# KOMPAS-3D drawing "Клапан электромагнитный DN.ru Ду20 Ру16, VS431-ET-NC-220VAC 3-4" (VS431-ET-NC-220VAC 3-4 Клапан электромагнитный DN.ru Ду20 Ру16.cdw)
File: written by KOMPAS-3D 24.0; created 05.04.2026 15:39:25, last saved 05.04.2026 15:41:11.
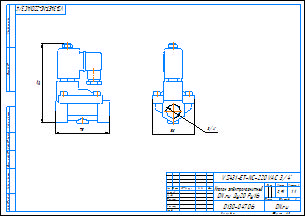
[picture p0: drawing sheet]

Document properties: c3d_UniqueCompID: ef56311e-7521-43dc-8291-0e6108b3d81d; Автор: artio; Класс точности: c; Знак неуказанной шероховатости: Шероховатость не задана; Рассекать на разрезах: Да; Автор: artio; Форматы листов документа: A3; Полное имя файла: VS431-ET-NC-220VAC 3-4 Клапан электромагнитный DN.ru Ду20 Ру16.m3d; Масса: 0.907; Наименование: Клапан электромагнитный DN.ru Ду20 Ру16; Количество листов документа: 1; Примечание: D130-04706

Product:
- Body: Тело 1  | qty 1
    Масса: 1.198355
- Part/product: Клапан электромагнитный DN.ru Ду20 Ру16  | designation VS431-ET-NC-220VAC 3-4
    Масса: 0.907
    Раздел спецификации: Прочие изделия
    Примечание: D130-04706
    additional columns: ef56311e-7521-43dc-8291-0e6108b3d81d; artio; c; Шероховатость не задана; Да

Views: Вид 1, Спереди, Проекционный вид 2
Referenced files in C:\Users\artio\OneDrive\Рабочий стол\Клапан электромагнитный DN.ru\VS431\VS431-ET-NC\: VS431-ET-NC-220VAC 3-4 Клапан электромагнитный DN.ru Ду20 Ру16.m3d
Referenced files in C:\Users\artio\OneDrive\Рабочий стол\Клапан электромагнитный DN.ru\VS431\VS431-ET-NC\VS431-ET-NC-220VAC\Ду20\: VS431-ET-NC-220VAC 3-4 Клапан электромагнитный DN.ru Ду20 Ру16.cdw, VS431-ET-NC-220VAC 3-4 Клапан электромагнитный DN.ru Ду20 Ру16.m3d
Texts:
  VS431-ET-NC-220VAC 3-4
  Клапан электромагнитный
  DN.ru Ду20 Ру16
  VS431-ET-NC-220VAC 3/4"
  VS431-ET-NC-220VAC 3/4"-
  Клапан электромагнитный DN.ru Ду20 Ру16
  VS431-ET-NC-220VAC 3-4 Клапан электромагнитный DN.ru Ду20 Ру16
Dimensions and other numbers on the sheet: 0; 3; 2; 4; 58; 3/4"; 75; 110; 1:1; 1; 0,91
